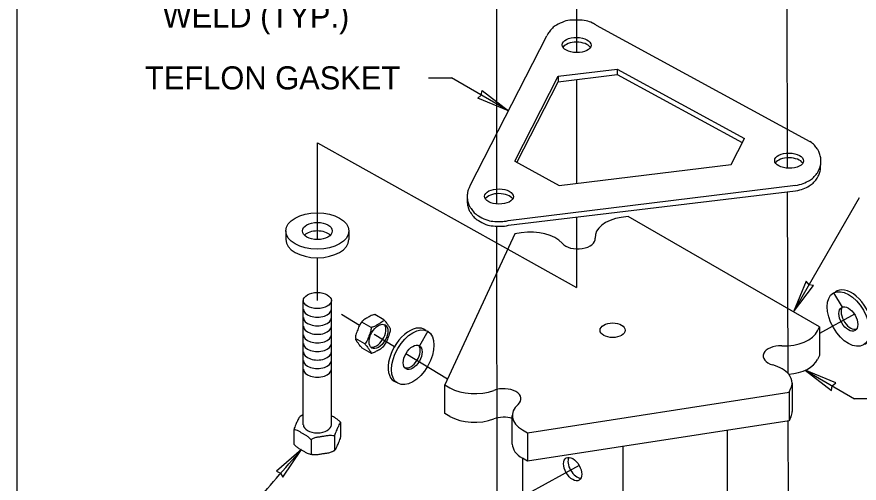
# Model space of a CAD drawing. Extents: x 99862 to 103151, y 99997 to 117076.
# Drawn here: x 99862 to 100446, y 112634 to 112958 of the extents above; entities that cross this region are included whole.
import ezdxf

# ---------------------------------------------------------------- set-up
doc = ezdxf.new("R2010")
doc.units = 0
for name, color, linetype in [('Level 1', 7, 'Continuous'), ('Level 12', 7, 'Continuous'), ('Level 13', 7, 'Continuous'), ('Level 15', 7, 'Continuous'), ('Level 20', 7, 'Continuous'), ('Level 4', 7, 'Continuous'), ('Level 6', 7, 'Continuous'), ('Level 8', 7, 'Continuous')]:
    doc.layers.add(name, color=color, linetype=linetype)

msp = doc.modelspace()

# ---------------------------------------------------------------- linework, layer by layer
at = {"layer": 'Level 1'}
msp.add_lwpolyline([(99862, 111999.5), (103151, 111999.5), (103151, 114075.5), (99862, 114075.5)], close=True, dxfattribs=at)
at = {"layer": 'Level 12'}
for p, q in [((100048.62, 112809.39), (100048.62, 112803.44)), ((100092.33, 112809.39), (100092.33, 112803.44)), ((100060.76, 112674.88), (100060.76, 112761.12)), ((100080.19, 112674.88), (100080.19, 112761.12)), ((100086.73, 112666.49), (100086.73, 112676.4)), ((100054.23, 112671.37), (100054.23, 112661.46)), ((100066.12, 112664.51), (100066.12, 112654.59)), ((100082.37, 112667.02), (100082.37, 112657.11))]:
    msp.add_line(p, q, dxfattribs=at)
for centre, major_axis in [((100070.48, 112809.39), (-21.85, 0)), ((100070.48, 112809.39), (-10.32, 0)), ((100070.48, 112761.12), (-9.71, 0))]:
    msp.add_ellipse(centre, major_axis=major_axis, ratio=0.57735, dxfattribs=at)
for centre, major_axis, start_param, end_param in [((100070.48, 112803.44), (-10.32, 0), 3.664192, 5.760586), ((100070.48, 112803.44), (21.85, 0), 3.141593, 6.283185), ((100070.48, 112755.17), (9.71, 0), 3.141588, 6.283185), ((100070.48, 112749.22), (9.71, 0), 3.141588, 6.283185), ((100070.48, 112743.28), (9.71, 0), 3.141588, 6.283185), ((100070.48, 112737.33), (9.71, 0), 3.141588, 6.283185), ((100070.48, 112731.38), (9.71, 0), 3.141588, 6.283185), ((100070.48, 112725.43), (9.71, 0), 3.141588, 6.283185), ((100070.48, 112719.49), (9.71, 0), 3.141588, 6.283185), ((100070.48, 112713.54), (9.71, 0), 3.141588, 6.283185), ((100070.48, 112674.88), (9.71, 0), 3.141593, 6.283185)]:
    msp.add_ellipse(centre, major_axis=major_axis, ratio=0.57735, start_param=start_param, end_param=end_param, dxfattribs=at)
for points, degree in [([(100058.46, 112680.71), (100058.4, 112680.67), (100058.33, 112680.62), (100057.71, 112679.95), (100057, 112678.33), (100056.4, 112677.05), (100055.81, 112675.77), (100055.1, 112674.32), (100054.43, 112672.17), (100054.32, 112671.77), (100054.23, 112671.37)], 3), ([(100059.18, 112681.12), (100058.96, 112681), (100058.75, 112680.88), (100058.52, 112680.74), (100058.49, 112680.73), (100058.46, 112680.71)], 3), ([(100060.76, 112681.79), (100060.41, 112681.67), (100060.06, 112681.54), (100059.55, 112681.31), (100059.37, 112681.22), (100059.18, 112681.12)], 3), ([(100086.73, 112676.4), (100086.47, 112676.74), (100086.16, 112677.08), (100084.35, 112678.84), (100082.4, 112679.88), (100080.78, 112680.82), (100080.59, 112680.93), (100080.39, 112681.05), (100080.19, 112681.16)], 3), ([(100086.73, 112676.4), (100086.63, 112676.39), (100086.52, 112676.31), (100085.86, 112675.6), (100085.14, 112673.98), (100084.55, 112672.7), (100083.95, 112671.41), (100083.24, 112669.96), (100082.58, 112667.81), (100082.47, 112667.42), (100082.37, 112667.02)], 3), ([(100066.12, 112664.51), (100065.86, 112664.85), (100065.56, 112665.18), (100063.75, 112666.95), (100061.8, 112667.99), (100060.18, 112668.93), (100058.55, 112669.86), (100056.6, 112671.07), (100054.79, 112671.4), (100054.49, 112671.42), (100054.23, 112671.37)], 3), ([(100082.37, 112667.02), (100082.02, 112667.16), (100081.6, 112667.25), (100079.13, 112667.59), (100076.47, 112667.09), (100074.25, 112666.75), (100072.03, 112666.4), (100069.37, 112666.08), (100066.89, 112664.98), (100066.48, 112664.75), (100066.12, 112664.51)], 3), ([(100082.5, 112657.16), (100082.56, 112657.19), (100082.62, 112657.25), (100083.24, 112657.91), (100083.95, 112659.53), (100084.55, 112660.81), (100085.14, 112662.09), (100085.86, 112663.55), (100086.52, 112665.69), (100086.63, 112666.09), (100086.73, 112666.49)], 3), ([(100054.23, 112661.46), (100054.49, 112661.12), (100054.79, 112660.79), (100056.6, 112659.02), (100058.55, 112657.98), (100060.18, 112657.04), (100061.78, 112656.12), (100063.69, 112654.93), (100065.22, 112654.63)], 3), ([(100065.21, 112654.63), (100065.96, 112654.48), (100066.72, 112654.37), (100067.46, 112654.29)], 2), ([(100065.22, 112654.63), (100065.24, 112654.63), (100065.26, 112654.62), (100065.56, 112654.57), (100065.86, 112654.55), (100066.12, 112654.59)], 3), ([(100066.12, 112654.59), (100066.48, 112654.45), (100066.89, 112654.36), (100067.33, 112654.3), (100067.4, 112654.29), (100067.46, 112654.29)], 3), ([(100067.46, 112654.29), (100069.53, 112654.06), (100072.1, 112654.53), (100074.25, 112654.86), (100076.47, 112655.21), (100079.13, 112655.54), (100081.4, 112656.55), (100081.59, 112656.64), (100081.77, 112656.74)], 3), ([(100081.77, 112656.74), (100081.99, 112656.86), (100082.2, 112656.98), (100082.44, 112657.12), (100082.47, 112657.14), (100082.5, 112657.15)], 3), ([(100081.77, 112656.74), (100081.98, 112656.85), (100082.18, 112656.98), (100082.37, 112657.11)], 2), ([(100082.37, 112657.11), (100082.41, 112657.11), (100082.45, 112657.13), (100082.5, 112657.16)], 2)]:
    msp.add_open_spline(points, degree=degree, dxfattribs=at)
at = {"layer": 'Level 13'}
for p, q in [((100428.49, 112766.34), (100434.65, 112756.5)), ((100116.71, 112747.63), (100110.27, 112751.34)), ((100107.79, 112742.48), (100101.35, 112746.19)), ((100103.33, 112730.98), (100096.89, 112734.7)), ((100147.05, 112739.76), (100141.27, 112729.74)), ((100101.35, 112728.35), (100107.79, 112724.63))]:
    msp.add_line(p, q, dxfattribs=at)
for centre, major_axis in [((100438.91, 112748.3), (-10.41, 18.04)), ((100438.91, 112748.3), (-4.63, 8.02)), ((100112.88, 112736.19), (-4.63, -8.02)), ((100136.64, 112721.72), (-10.41, -18.04)), ((100136.64, 112721.72), (-4.63, -8.02))]:
    msp.add_ellipse(centre, major_axis=major_axis, ratio=0.57735, dxfattribs=at)
for centre, major_axis, start_param, end_param in [((100441.05, 112749.52), (-10.41, 18.04), 3.035348, 6.38194), ((100440.43, 112749.61), (-4.63, 8.02), 0.295844, 3.063613), ((100111.53, 112737.23), (-4.63, -8.02), 0.083455, 2.907882), ((100134.32, 112723), (-10.41, -18.04), 3.042453, 6.404476), ((100135.29, 112722.75), (-4.63, -8.02), 0.083455, 2.907882)]:
    msp.add_ellipse(centre, major_axis=major_axis, ratio=0.57735, start_param=start_param, end_param=end_param, dxfattribs=at)
for points, degree in [([(100101.72, 112746.77), (100101.34, 112746.34), (100100.98, 112745.89), (100100.65, 112745.44)], 2), ([(100110.27, 112751.34), (100109.95, 112751.3), (100109.62, 112751.23), (100107.8, 112750.72), (100106.39, 112749.84), (100105.17, 112749.14), (100103.97, 112748.45), (100102.48, 112747.65), (100101.72, 112746.77)], 3), ([(100116.71, 112747.63), (100116.64, 112747.44), (100116.52, 112747.25), (100115.63, 112746.2), (100114.11, 112745.39), (100112.89, 112744.68), (100111.67, 112743.98), (100110.27, 112743.1), (100108.44, 112742.59), (100108.11, 112742.52), (100107.79, 112742.48)], 3), ([(100121.19, 112741.38), (100121.19, 112741.43), (100121.17, 112741.49), (100120.98, 112742.15), (100120.19, 112743.22), (100119.58, 112744.08), (100118.97, 112744.95), (100118.3, 112745.96), (100117.15, 112747.19), (100116.93, 112747.42), (100116.71, 112747.63)], 3), ([(100100.65, 112745.44), (100099.72, 112744.18), (100099.07, 112742.34), (100098.48, 112740.81), (100097.87, 112739.24), (100097.09, 112737.39), (100096.89, 112735.54), (100096.88, 112735.38), (100096.88, 112735.22)], 3), ([(100107.79, 112742.48), (100107.82, 112742.15), (100107.81, 112741.8), (100107.6, 112739.78), (100106.81, 112737.93), (100106.2, 112736.36), (100105.59, 112734.79), (100104.92, 112732.87), (100103.77, 112731.39), (100103.55, 112731.16), (100103.33, 112730.98)], 3), ([(100117.41, 112730.54), (100118.34, 112731.79), (100118.99, 112733.64), (100119.58, 112735.16), (100120.19, 112736.73), (100120.98, 112738.59), (100121.17, 112740.44), (100121.18, 112740.6), (100121.19, 112740.75)], 3), ([(100121.19, 112740.75), (100121.19, 112740.94), (100121.19, 112741.12), (100121.19, 112741.33), (100121.19, 112741.35), (100121.19, 112741.38)], 3), ([(100096.88, 112734.6), (100096.88, 112734.54), (100096.89, 112734.48), (100097.09, 112733.83), (100097.87, 112732.76), (100098.48, 112731.89), (100099.09, 112731.03), (100099.77, 112730.02), (100100.91, 112728.78), (100101.13, 112728.56), (100101.35, 112728.35)], 3), ([(100103.33, 112730.98), (100103.55, 112730.77), (100103.77, 112730.55), (100104.92, 112729.31), (100105.59, 112728.3), (100106.2, 112727.44), (100106.81, 112726.57), (100107.6, 112725.5), (100107.81, 112724.8), (100107.82, 112724.7), (100107.79, 112724.63)], 3), ([(100107.79, 112724.63), (100108.11, 112724.67), (100108.44, 112724.75), (100110.27, 112725.26), (100111.67, 112726.14), (100112.89, 112726.84), (100114.09, 112727.53), (100115.58, 112728.33), (100116.35, 112729.21)], 3), ([(100116.35, 112729.21), (100116.72, 112729.64), (100117.08, 112730.09), (100117.41, 112730.54)], 2)]:
    msp.add_open_spline(points, degree=degree, dxfattribs=at)
at = {"layer": 'Level 15'}
for p, q in [((100396.73, 112852.91), (100395.89, 113194.51)), ((100250.38, 113103.78), (100250.38, 112933.13)), ((100194.62, 113046.03), (100194.85, 112828.12)), ((100147.54, 112915.62), (100163.54, 112915.62)), ((100203.08, 112892.79), (100163.54, 112915.62)), ((100250.38, 112914.45), (100250.38, 112842.36)), ((100070.48, 112803.43), (100070.48, 112870.62)), ((100397.08, 112710.46), (100396.77, 112836.6)), ((100400.81, 112753.24), (100446.69, 112832.7)), ((100250.38, 112818.99), (100250.38, 112770.16)), ((100194.87, 112812.71), (100195.15, 112553.35)), ((100070.48, 112761.12), (100070.48, 112790.82)), ((100099.7, 112743.8), (100087.28, 112751.38)), ((100443.14, 112751.63), (100418.86, 112738.3)), ((100123.92, 112729.04), (100109.85, 112737.61)), ((100160.73, 112706.59), (100131.89, 112724.18)), ((100408.87, 112712.72), (100443.06, 112692.97)), ((100459.06, 112692.97), (100443.06, 112692.97)), ((100397.47, 112553.36), (100397.16, 112677.54)), ((100252.09, 112646.72), (100181.73, 112608.09))]:
    msp.add_line(p, q, dxfattribs=at)
for points in [[(100203.08, 112892.79), (100181.82, 112901.62), (100184.23, 112903.68), (100184.8, 112906.79)], [(100400.81, 112753.24), (100414.81, 112771.52), (100411.7, 112772.1), (100409.64, 112774.51)], [(100408.87, 112712.72), (100427.15, 112698.72), (100427.72, 112701.83), (100430.13, 112703.89)], [(100059.5, 112657.65), (100042.05, 112642.62), (100044.98, 112641.42), (100046.5, 112638.64)]]:
    msp.add_lwpolyline(points, close=True, dxfattribs=at)
msp.add_lwpolyline([(100070.48, 112870.62), (100250.38, 112770.16)], dxfattribs=at)
msp.add_open_spline([(100325.17, 112301.86), (99735.04, 112301.86), (100059.37, 112657.5)], degree=2, dxfattribs=at)
at = {"layer": 'Level 4'}
msp.add_line((100282.77, 112386.45), (100282.77, 112659.75), dxfattribs=at)
for points in [[(100355.06, 112427.85), (100355.06, 112671.03)], [(100212.71, 112651.71), (100212.71, 112566.85)]]:
    msp.add_lwpolyline(points, dxfattribs=at)
msp.add_ellipse((100247.64, 112644.15), major_axis=(4.45, -7.71), ratio=0.57735, dxfattribs=at)
msp.add_ellipse((100250.66, 112645.9), major_axis=(-4.45, 7.71), ratio=0.57735, start_param=0.346291, end_param=2.795302, dxfattribs=at)
at = {"layer": 'Level 6'}
for p, q in [((100286.05, 112819.5), (100281.24, 112818.76)), ((100418.86, 112742.82), (100286.05, 112819.5)), ((100207.49, 112807.35), (100158.88, 112702.61)), ((100212, 112808.05), (100207.49, 112807.35)), ((100417.57, 112740.05), (100418.86, 112742.82)), ((100418.86, 112742.82), (100418.86, 112723)), ((100418.86, 112723), (100417.57, 112720.22)), ((100158.88, 112702.61), (100162.41, 112700.57)), ((100158.88, 112682.78), (100158.88, 112702.61)), ((100397.81, 112697.47), (100399.1, 112700.25)), ((100399.93, 112703.87), (100399.93, 112684.05)), ((100216.4, 112669.4), (100397.81, 112697.47)), ((100397.81, 112697.47), (100397.81, 112677.64)), ((100162.41, 112680.75), (100158.88, 112682.78)), ((100205.76, 112661.53), (100205.76, 112681.35)), ((100397.81, 112677.64), (100216.4, 112649.58)), ((100399.1, 112680.42), (100397.81, 112677.64)), ((100212.87, 112671.44), (100216.4, 112669.4)), ((100216.4, 112669.4), (100216.4, 112649.58)), ((100216.4, 112649.58), (100212.87, 112651.61))]:
    msp.add_line(p, q, dxfattribs=at)
for centre, major_axis, start_param, end_param in [((100287.53, 112805.22), (-24.28, 0), 4.974189, 6.343627), ((100218.59, 112794.55), (-24.28, 0), 3.604667, 4.987015), ((100251.17, 112803.95), (-12.14, 0), 0.463321, 3.201871), ((100394.12, 112743.67), (-24.28, 0), 1.510356, 2.879794), ((100391.92, 112722.69), (-12.14, 0), 4.652112, 7.390662), ((100394.12, 112723.85), (-24.28, 0), 1.711023, 2.879794), ((100375.65, 112703.87), (-24.28, 0), 3.591411, 4.249233), ((100375.65, 112703.87), (-24.28, 0), 3.141593, 3.591411), ((100179.58, 112710.49), (-24.28, 0), 0.785398, 2.154673), ((100199.66, 112692.94), (-12.14, 0), 2.557552, 5.296429), ((100375.65, 112703.87), (-24.28, 0), 2.879794, 3.141593), ((100230.04, 112681.35), (-24.28, 0), 5.699308, 7.068583), ((100375.65, 112684.05), (-24.28, 0), 2.879794, 3.141593), ((100179.58, 112690.66), (-24.28, 0), 0.785398, 2.154673), ((100199.66, 112673.12), (-12.14, 0), 4.185432, 5.296429), ((100230.04, 112661.53), (-24.28, 0), 0, 0.785398)]:
    msp.add_ellipse(centre, major_axis=major_axis, ratio=0.57735, start_param=start_param, end_param=end_param, dxfattribs=at)
msp.add_ellipse((100275.36, 112740.49), major_axis=(-8.75, 0), ratio=0.57735, dxfattribs=at)
at = {"layer": 'Level 8'}
for p, q in [((100263.96, 112952.24), (100412.27, 112871.42)), ((100176.49, 112840.83), (100229.67, 112944.76)), ((100237.58, 112916.69), (100278.52, 112921.73)), ((100278.52, 112921.73), (100278.52, 112917.91)), ((100278.52, 112921.73), (100366.74, 112873.65)), ((100207.4, 112857.72), (100237.58, 112916.69)), ((100237.58, 112912.88), (100278.52, 112917.91)), ((100237.58, 112916.69), (100237.58, 112912.88)), ((100278.52, 112917.91), (100365.22, 112870.67)), ((100208.93, 112856.89), (100237.58, 112912.88)), ((100357.48, 112855.54), (100366.74, 112873.65)), ((100207.4, 112857.72), (100238.31, 112840.88)), ((100238.31, 112840.88), (100357.48, 112855.54)), ((100202.83, 112816.54), (100402.12, 112841.05)), ((100203.14, 112813.31), (100402.12, 112837.24)), ((100174.49, 112832.07), (100174.49, 112829.89))]:
    msp.add_line(p, q, dxfattribs=at)
for centre in [(100250.38, 112938.4), (100397.79, 112858.14), (100196.51, 112833.3)]:
    msp.add_ellipse(centre, major_axis=(10.01, -0.15), ratio=0.526809, dxfattribs=at)
for centre in [(100250.46, 112935.11), (100397.87, 112854.85), (100196.58, 112830.01)]:
    msp.add_ellipse(centre, major_axis=(10.01, -0.15), ratio=0.526809, start_param=0.33789, end_param=2.844208, dxfattribs=at)
for points, degree in [([(100263.96, 112952.24), (100263.74, 112952.37), (100263.52, 112952.5), (100259.2, 112954.85), (100254.92, 112955.68), (100246.34, 112955.8), (100242.05, 112955.11), (100235.81, 112951.94), (100233.66, 112950.47), (100230.99, 112947.17), (100230.26, 112946.05), (100229.67, 112944.76)], 3), ([(100419.87, 112857.81), (100419.89, 112859.67), (100419.56, 112861.51), (100418.39, 112864.74), (100417.57, 112866.16), (100415.32, 112869.1), (100413.8, 112870.41), (100412.27, 112871.42)], 3), ([(100401.64, 112840.99), (100404.55, 112841.33), (100407.45, 112842.11), (100412.36, 112844.61), (100414.51, 112846.08), (100417.32, 112849.55), (100418.18, 112850.93), (100419.45, 112854.14), (100419.84, 112855.96), (100419.87, 112857.81)], 3), ([(100402.12, 112837.24), (100404.8, 112837.61), (100407.45, 112838.38), (100412.14, 112840.76), (100414.29, 112842.23), (100417.11, 112845.71), (100417.96, 112847.08), (100419.23, 112850.3), (100419.62, 112852.11), (100419.65, 112853.97)], 3), ([(100419.65, 112853.97), (100419.65, 112854.41), (100419.64, 112854.85), (100419.61, 112855.28)], 2), ([(100176.49, 112840.83), (100176.14, 112840.21), (100175.81, 112839.55), (100174.91, 112837.24), (100174.52, 112835.43), (100174.46, 112831.73), (100174.8, 112829.9), (100175.96, 112826.67), (100176.78, 112825.26), (100179.48, 112821.72), (100181.58, 112820.19), (100187.73, 112816.83), (100191.96, 112816.02), (100198.47, 112815.92), (100200.66, 112816.09), (100202.83, 112816.54)], 3), ([(100174.49, 112830.26), (100174.47, 112828.42), (100174.8, 112826.6), (100175.97, 112823.37), (100176.78, 112821.97), (100179.48, 112818.42), (100181.58, 112816.9), (100187.74, 112813.54), (100191.96, 112812.72), (100198.57, 112812.63), (100200.86, 112812.81), (100203.14, 112813.31)], 3)]:
    msp.add_open_spline(points, degree=degree, dxfattribs=at)

# ---------------------------------------------------------------- texts
at = {"layer": 'Level 20'}
for s, p in [('WELD (TYP.)', (99963.07, 112950.55)), ('TEFLON GASKET', (99950.88, 112907.63))]:
    msp.add_text(s, height=16, dxfattribs=at).set_placement(p)

doc.saveas('drawing.dxf')
